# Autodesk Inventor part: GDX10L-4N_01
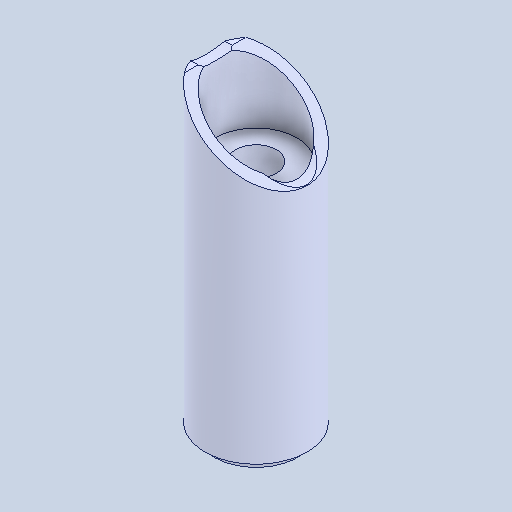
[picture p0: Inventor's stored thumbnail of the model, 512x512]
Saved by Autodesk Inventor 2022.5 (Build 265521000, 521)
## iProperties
Created: 2024-06
Part Number: GDX10L-4N_01
Material: 一般
Document SubType Name: Modeling
Designer: ImaoCorp
Density: 1 g/cm^3
Appearance: 既定
Author: ImaoCorp
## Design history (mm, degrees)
feature "GDX10L-4N_01"
node "ソリッド1"
